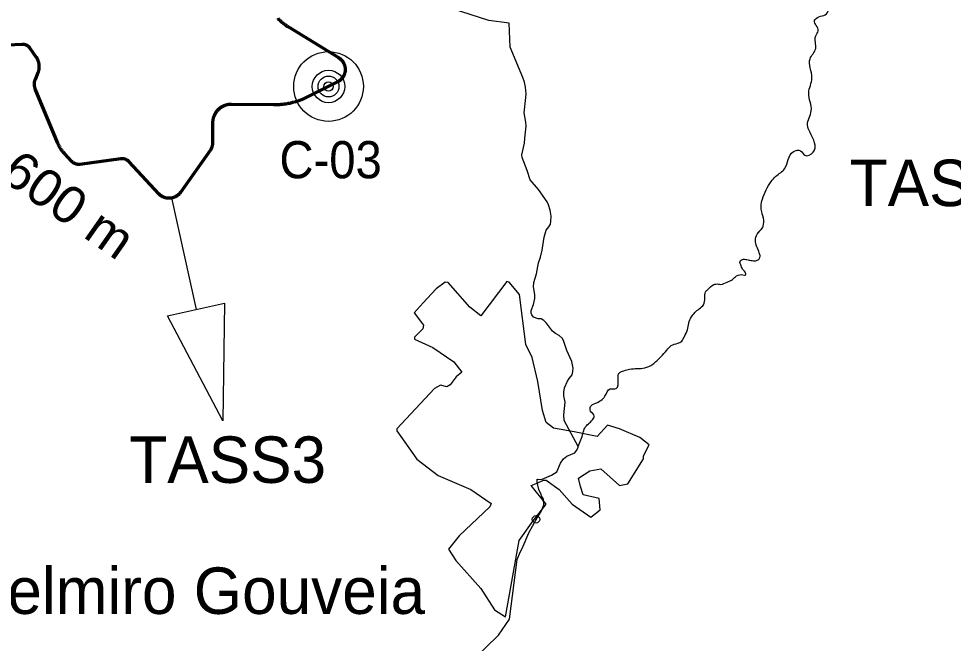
# Model space of a CAD drawing. Extents: x -1643653 to 4543381, y 1624270 to 13878484.
# Drawn here: x 604414 to 614474, y 8960089 to 8966810 of the extents above; entities that cross this region are included whole.
import ezdxf
from ezdxf.enums import TextEntityAlignment as Align

# ---------------------------------------------------------------- set-up
doc = ezdxf.new("R2010")
doc.units = 0
doc.header["$LTSCALE"] = 160
doc.header["$PDMODE"] = 32
doc.header["$PDSIZE"] = 80
for name, color, linetype, lineweight in [('15', 7, 'Continuous', 25), ('21', 7, 'Continuous', 25), ('24', 7, 'Continuous', 25), ('50', 7, 'Continuous', 13), ('54', 7, 'Continuous', 25), ('60', 7, 'Continuous', 13), ('61', 7, 'Continuous', 70)]:
    doc.layers.add(name, color=color, linetype=linetype, lineweight=lineweight)
doc.layers.add('41', color=7, linetype='Continuous')

msp = doc.modelspace()

# ---------------------------------------------------------------- linework, layer by layer
at = {"layer": '15'}
for radius in [375, 175, 112.5, 50]:
    msp.add_circle((607748.5, 8966080.3), radius, dxfattribs=at)
at = {"layer": '21'}
for points in [[(609804.3, 8963841.6), (609692.8, 8963976.2), (609666.6, 8963982.7), (609387.8, 8963613.5), (609268.7, 8963704.3), (609037.7, 8963969.7), (609005.2, 8963976.3), (608907.9, 8963902.9), (608765.2, 8963749.4), (608768.4, 8963752.9)], [(609800.8, 8961196.1), (609951.3, 8961405.5), (610091.2, 8961585.5), (609931.3, 8961785.4), (610001.3, 8961815.4), (610061.2, 8961845.4), (610091.2, 8961845.4), (610231.1, 8961745.4), (610371.1, 8961585.5), (610570.9, 8961445.5), (610670.8, 8961525.5), (610660.9, 8961645.5), (610491, 8961685.5), (610461, 8961775.4), (610441, 8961865.4), (610560.9, 8961945.4), (610680.8, 8961965.4), (610880.7, 8961785.4), (610970.7, 8961805.4), (611140.5, 8962075.3), (611140.5, 8962105.3), (611200.5, 8962225.3), (611100.6, 8962305.2), (610880.7, 8962395.2), (610750.8, 8962435.2), (610640.9, 8962315.2), (610391, 8962365.2), (610171.2, 8962405.2), (610091.2, 8962465.2), (610051.2, 8962595.2), (610001.3, 8962905.1), (609941.3, 8963165), (609871.4, 8963304.9), (609804.3, 8963841.6)], [(608768.4, 8963752.9), (608671.8, 8963644.5), (608771.6, 8963513.5), (608763, 8963472.8), (608674.7, 8963384.3), (608674.6, 8963362.6), (608871.1, 8963271.6), (609098.6, 8963116.9), (609185.2, 8963006.2), (609122.6, 8962955.4), (609059.5, 8962870.7), (609020.3, 8962848.1), (608953.3, 8962867.3), (608890.2, 8962830.9), (608482.3, 8962396.3), (608482.2, 8962374.6), (608698.7, 8962069.7), (608927.4, 8961894.7), (609281.9, 8961745.5), (609500, 8961592.1), (609485, 8961557.5), (609154.4, 8961246.1), (609040.8, 8961101.4), (609119, 8960979.5), (609387.8, 8960677.5), (609534.3, 8960449.1), (609653.8, 8960372.8), (609800.8, 8961196.1)]]:
    msp.add_lwpolyline(points, dxfattribs=at)
at = {"layer": '24'}
for points in [[(609474.2, 8966790.4), (608973.4, 8966950.1), (608864.6, 8966990.5), (608731.8, 8967057), (608620.3, 8967109.1), (608563.4, 8967149.5), (608515.8, 8967162.6)], [(609841.5, 8966176.9), (609704.1, 8966503.7), (609693, 8966762.7), (609474.2, 8966790.4)], [(610371.4, 8962976.2), (610379.8, 8963013.8), (610382.1, 8963047.9), (610367.5, 8963120), (610314.8, 8963239.1), (610282.3, 8963338.2), (610265.4, 8963370.2), (610232.8, 8963402.2), (610193.3, 8963421.2), (610157.8, 8963448.2), (610095.6, 8963532.2), (610066.7, 8963561.2), (610036.6, 8963580.2), (610003.6, 8963581.1), (609956.2, 8963599.1), (609936, 8963623.1), (609928.6, 8963640.1), (609929.5, 8963669.1), (609954.4, 8963735.3), (609968.3, 8963800.4), (609967.7, 8963842.5), (609955.3, 8963923.6), (609957.6, 8963969.7), (609987.3, 8964065.8), (610009.7, 8964184.1), (610029.9, 8964242.2), (610049.4, 8964318.3), (610070.6, 8964459.6), (610090.6, 8964534.7), (610118.8, 8964569.8), (610136.5, 8964599.9), (610143.2, 8964627), (610143.3, 8964686.1), (610132.5, 8964751.1), (610117.5, 8964805.2), (610101.9, 8964839.2), (610009.9, 8964971.3), (609920.5, 8965076.3), (609887.1, 8965177.4), (609832.3, 8965315.6), (609830, 8965343.6), (609859.8, 8965469.8), (609861.1, 8965523.9), (609875.2, 8965654.1), (609872.3, 8965696.2), (609853, 8965796.3), (609874, 8965961.6), (609874.8, 8965999.7), (609869.2, 8966072.8), (609858.8, 8966126.9), (609841.5, 8966176.9)], [(609982.1, 8961422.7), (610037.1, 8961507.9), (610064.5, 8961578.1), (610064.2, 8961638.2), (610040.6, 8961677.2), (610038.1, 8961690.2), (610013.3, 8961743.3), (609992.6, 8961823.3), (609993.5, 8961853.4), (609997.6, 8961856.4), (610025.7, 8961851.5), (610048.1, 8961855.5), (610148.5, 8961896.7), (610207.6, 8961933.9), (610245.1, 8962026.1), (610277.6, 8962073.2), (610312.8, 8962103.3), (610398.6, 8962138.5), (610419.5, 8962164.6), (610435.7, 8962195.6), (610437.2, 8962206.7), (610284.5, 8962485.8), (610279.8, 8962547.9), (610295.5, 8962684.2), (610281.3, 8962752.3), (610279.8, 8962791.3), (610289, 8962838.4), (610320, 8962910.6), (610338.8, 8962938.6), (610371.4, 8962976.2)], [(609306.9, 8959910.2), (609576.6, 8960175.8), (609697.7, 8960350), (609780.5, 8960992), (609809.8, 8961070.9), (609834, 8961110), (609904.8, 8961278.4), (609982.1, 8961422.7)]]:
    msp.add_lwpolyline(points, dxfattribs=at)
msp.add_spline([(610437.2, 8962206.7), (610489.2, 8962352.5), (610507, 8962405.6), (610591.1, 8962494.2), (610608.8, 8962534.1), (610569, 8962587.3), (610569, 8962636), (610622.1, 8962671.5), (610723.9, 8962746.8), (610781.5, 8962826.6), (610843.5, 8962831), (610865.6, 8962932.9), (610878.9, 8962999.4), (610927.6, 8963021.5), (610989.6, 8963039.3), (611153.5, 8963052.6), (611237.6, 8963092.4), (611326.2, 8963170.3), (611391.1, 8963243.8), (611437.2, 8963291.6), (611507.3, 8963317.3), (611551.7, 8963341.2), (611579, 8963390.8), (611611.5, 8963460.9), (611625.2, 8963534.4), (611655.9, 8963601), (611737.9, 8963688.2), (611785.7, 8963732.7), (611797.7, 8963804.5), (611808, 8963871.1), (611830.2, 8963895.1), (611896.8, 8963948.1), (611919, 8963954.9), (611970.2, 8963951.5), (612038.6, 8963975.4), (612098.4, 8964004.5), (612127.4, 8964033.5), (612190.6, 8964055.8), (612224.8, 8964050.6), (612238.5, 8964052.3), (612240.2, 8964069.4), (612206, 8964115.6), (612185.5, 8964161.7), (612177, 8964187.4), (612183.8, 8964207.9), (612226.5, 8964221.6), (612276, 8964211.3), (612310.2, 8964206.2), (612354.6, 8964207.9), (612385.4, 8964225), (612393.9, 8964254), (612385.4, 8964289.9), (612343.5, 8964423.3), (612364, 8964491.7), (612418.7, 8964560.1), (612432.3, 8964642.1), (612411.8, 8964731), (612405, 8964792.5), (612418.7, 8964867.8), (612514.3, 8965059.2), (612562.2, 8965113.9), (612657.8, 8965196), (612753.5, 8965380.6), (612828.7, 8965387.4), (612876.5, 8965339.6), (612965.4, 8965373.7), (612931.2, 8965585.7), (612903.9, 8965667.8), (612944.9, 8965818.2), (612917.5, 8966009.7), (612951.7, 8966173.8), (612931.2, 8966378.9), (612992.7, 8966488.3), (612992.7, 8966625.1), (613020, 8966679.8), (612979, 8966789.2), (613026.9, 8966830.2), (613095.2, 8966850.7), (613136.2, 8967014.8), (613067.9, 8967213.1), (612965.4, 8967261), (612938, 8967343), (612883.4, 8967397.7), (612787.7, 8967425.1), (612753.5, 8967452.4), (612705.7, 8967520.8), (612658.6, 8967543.9), (612640.1, 8967590.1), (612640.1, 8967642.6), (612667.9, 8967707.3), (612667.9, 8967747.4)], degree=3, dxfattribs=at)
msp.add_point((609982.1, 8961422.7), dxfattribs=at)
at = {"layer": '54'}
msp.add_line((606056.9, 8964881.6), (606322.4, 8963679.5), dxfattribs=at)
msp.add_lwpolyline([(606630.7, 8963747.6), (606609.7, 8962482.2), (606014.1, 8963611.4)], close=True, dxfattribs=at)
at = {"layer": '60', "lineweight": 25}
msp.add_spline([(814781, 9009175.5), (814787.2, 9009173.4), (814796.9, 9009173.4), (814799.4, 9009172.4), (814805.1, 9009174.5), (814805.6, 9009176.5), (814811.7, 9009179.5), (814811.7, 9009179.5), (814801.5, 9009181), (814790.7, 9009181.5), (814784.1, 9009183.1), (814777.4, 9009185.1), (814778.4, 9009175.5)], degree=3, dxfattribs=at)
at = {"layer": '61'}
for points in [[(607201.7, 8966814), (607206.5, 8966809.1), (607211.4, 8966804.2), (607216.4, 8966799.4), (607221.4, 8966794.6), (607226.5, 8966789.9), (607231.6, 8966785.3), (607236.8, 8966780.7), (607242.1, 8966776.1), (607247.3, 8966771.7), (607252.7, 8966767.2), (607258.1, 8966762.9), (607263.5, 8966758.6), (607269, 8966754.4), (607274.6, 8966750.2), (607280.2, 8966746.1), (607285.8, 8966742.1), (607291.5, 8966738.2), (607297.2, 8966734.2), (607303, 8966730.4), (607308.8, 8966726.7), (607314.7, 8966723), (607318.3, 8966720.7), (607318.3, 8966720.7), (607856.3, 8966390.9), (607856.3, 8966390.9), (607859.2, 8966389), (607862.1, 8966387.1), (607864.9, 8966385.1), (607867.7, 8966383.1), (607870.5, 8966381), (607873.2, 8966378.8), (607875.8, 8966376.6), (607878.4, 8966374.3), (607881, 8966371.9), (607883.5, 8966369.5), (607885.9, 8966367.1), (607888.3, 8966364.5), (607890.6, 8966362), (607892.8, 8966359.3), (607895, 8966356.6), (607897.2, 8966353.9), (607899.2, 8966351.1), (607901.2, 8966348.3), (607903.2, 8966345.4), (607905, 8966342.5), (607906.8, 8966339.6), (607908.6, 8966336.6), (607910.2, 8966333.5), (607911.8, 8966330.5), (607913.3, 8966327.3), (607914.8, 8966324.2), (607916.2, 8966321), (607917.5, 8966317.8), (607918.7, 8966314.6), (607919.9, 8966311.3), (607920.9, 8966308), (607921.9, 8966304.7), (607922.9, 8966301.3), (607923.7, 8966298), (607924.5, 8966294.6), (607925.2, 8966291.2), (607925.8, 8966287.8), (607926.3, 8966284.4), (607926.8, 8966281), (607927.2, 8966277.5), (607927.5, 8966274.1), (607927.7, 8966270.6), (607927.8, 8966267.1), (607927.9, 8966263.7), (607927.8, 8966260.2), (607927.7, 8966256.8), (607927.6, 8966253.3), (607927.3, 8966249.8), (607926.9, 8966246.4), (607926.5, 8966243), (607926, 8966239.5), (607925.4, 8966236.1), (607924.8, 8966232.7), (607924, 8966229.3), (607923.2, 8966226), (607922.3, 8966222.6), (607921.3, 8966219.3), (607920.3, 8966216), (607919.2, 8966212.7), (607918, 8966209.5), (607916.7, 8966206.2), (607915.4, 8966203), (607913.9, 8966199.9), (607912.5, 8966196.8), (607910.9, 8966193.7), (607909.2, 8966190.6), (607907.5, 8966187.6), (607905.8, 8966184.6), (607903.9, 8966181.7), (607902, 8966178.8), (607900, 8966176), (607898, 8966173.2)], [(604629, 8966245.2), (604630, 8966248.8), (604630.8, 8966252.5), (604631.7, 8966256.2), (604632.4, 8966260), (604633.1, 8966263.7), (604633.7, 8966267.4), (604634.2, 8966271.2), (604634.7, 8966275), (604635, 8966278.7), (604635.3, 8966282.5), (604635.5, 8966286.3), (604635.6, 8966290.1), (604635.6, 8966293.9), (604635.6, 8966297.7), (604635.5, 8966301.5), (604635.3, 8966305.3), (604635, 8966309.1), (604634.6, 8966312.8), (604634.2, 8966316.6), (604633.6, 8966320.4), (604633, 8966324.1), (604632.4, 8966327.8), (604631.6, 8966331.6), (604630.8, 8966335.3), (604629.8, 8966339), (604628.9, 8966342.6), (604627.8, 8966346.2), (604626.6, 8966349.9), (604625.4, 8966353.5), (604624.1, 8966357), (604622.8, 8966360.6), (604621.3, 8966364.1), (604619.8, 8966367.6), (604618.2, 8966371), (604616.5, 8966374.4), (604614.8, 8966377.8), (604613, 8966381.1), (604611.1, 8966384.4), (604609.2, 8966387.7), (604607.1, 8966390.9), (604605.1, 8966394.1), (604603.5, 8966396.4), (604603.5, 8966396.4), (604538.6, 8966489.8), (604536.9, 8966492.1), (604535.2, 8966494.3), (604533.5, 8966496.6), (604531.6, 8966498.7), (604529.7, 8966500.8), (604527.8, 8966502.8), (604525.8, 8966504.8), (604523.7, 8966506.8), (604521.6, 8966508.7), (604519.4, 8966510.5), (604517.2, 8966512.2), (604514.9, 8966513.9), (604512.6, 8966515.5), (604510.2, 8966517.1), (604507.8, 8966518.6), (604505.4, 8966520), (604502.9, 8966521.3), (604500.4, 8966522.6), (604497.8, 8966523.8), (604495.2, 8966524.9), (604492.6, 8966526), (604489.9, 8966527), (604487.3, 8966527.9), (604484.6, 8966528.7), (604481.8, 8966529.5), (604479.1, 8966530.2), (604476.3, 8966530.8), (604473.6, 8966531.3), (604470.8, 8966531.7), (604468, 8966532.1), (604465.1, 8966532.4), (604462.3, 8966532.6), (604459.5, 8966532.7), (604456.7, 8966532.8), (604453.8, 8966532.7), (604451.6, 8966532.6), (604451.6, 8966532.6), (604208.1, 8966520.9)], [(605060.5, 8965241.8), (605057.7, 8965241.8), (605054.9, 8965241.9), (605052.1, 8965242), (605049.2, 8965242.3), (605046.4, 8965242.6), (605043.6, 8965243), (605040.8, 8965243.4), (605038.1, 8965244), (605035.3, 8965244.6), (605032.6, 8965245.3), (605029.8, 8965246.1), (605027.1, 8965246.9), (605024.5, 8965247.8), (605021.8, 8965248.8), (605019.2, 8965249.9), (605016.6, 8965251.1), (605014.1, 8965252.3), (605011.6, 8965253.6), (605009.1, 8965254.9), (605006.6, 8965256.4), (605004.2, 8965257.9), (605001.9, 8965259.4), (604999.6, 8965261.1), (604997.3, 8965262.8), (604995.1, 8965264.5), (604992.9, 8965266.4), (604990.8, 8965268.2), (604988.8, 8965270.2), (604986.8, 8965272.2), (604985.2, 8965273.9), (604907.2, 8965358.2), (604903.3, 8965362.3), (604899.6, 8965366.6), (604895.9, 8965370.8), (604892.3, 8965375.2), (604888.7, 8965379.6), (604885.2, 8965384), (604881.7, 8965388.5), (604878.4, 8965393), (604875, 8965397.6), (604871.8, 8965402.2), (604868.6, 8965406.9), (604865.5, 8965411.6), (604862.4, 8965416.4), (604859.4, 8965421.2), (604856.5, 8965426), (604853.7, 8965430.9), (604850.9, 8965435.8), (604848.2, 8965440.8), (604845.6, 8965445.8), (604843, 8965450.9), (604840.5, 8965455.9), (604838.1, 8965461.1), (604835.7, 8965466.2), (604833.4, 8965471.4), (604831.2, 8965476.6), (604830.8, 8965477.7), (604592.6, 8966056.5), (604592.6, 8966056.5), (604591.4, 8966059.5), (604590.3, 8966062.5), (604589.3, 8966065.6), (604588.3, 8966068.6), (604587.4, 8966071.7), (604586.6, 8966074.8), (604585.9, 8966078), (604585.2, 8966081.1), (604584.7, 8966084.3), (604584.2, 8966087.5), (604583.7, 8966090.7), (604583.4, 8966093.9), (604583.2, 8966097.1), (604583, 8966100.3), (604582.9, 8966103.6), (604582.8, 8966106.8), (604582.9, 8966110), (604583.1, 8966113.2), (604583.3, 8966116.5), (604583.6, 8966119.7), (604584, 8966122.9), (604584.4, 8966126.1), (604585, 8966129.2), (604585.6, 8966132.4), (604586.3, 8966135.6), (604587, 8966138.7), (604587.9, 8966141.8), (604588.8, 8966144.9), (604589.8, 8966148), (604590.9, 8966151), (604592.1, 8966154), (604593.1, 8966156.5), (604593.1, 8966156.5), (604621.5, 8966223.7), (604621.5, 8966223.7), (604622.9, 8966227.2), (604624.3, 8966230.8), (604625.6, 8966234.3), (604626.8, 8966237.9), (604627.9, 8966241.5), (604629, 8966245.2)], [(607898, 8966173.2), (607895.9, 8966170.4), (607893.7, 8966167.7), (607891.5, 8966165.1), (607889.2, 8966162.5), (607886.8, 8966159.9), (607884.4, 8966157.4), (607882, 8966155), (607879.5, 8966152.6), (607876.9, 8966150.3), (607874.2, 8966148.1), (607871.6, 8966145.8), (607868.8, 8966143.7), (607866.1, 8966141.7), (607863.2, 8966139.7), (607860.4, 8966137.7), (607857.5, 8966135.8), (607854.5, 8966134), (607851.5, 8966132.3), (607848.5, 8966130.6), (607845.4, 8966129), (607845.2, 8966129), (607524, 8965967.5), (607516.8, 8965963.9), (607509.6, 8965960.4), (607502.4, 8965957), (607495.1, 8965953.7), (607487.8, 8965950.4), (607480.5, 8965947.2), (607473.1, 8965944.1), (607465.7, 8965941), (607458.3, 8965938.1), (607450.8, 8965935.2), (607443.4, 8965932.3), (607435.8, 8965929.6), (607428.3, 8965926.9), (607420.7, 8965924.3), (607413.2, 8965921.8), (607405.5, 8965919.4), (607397.9, 8965917), (607390.2, 8965914.7), (607382.5, 8965912.5), (607374.8, 8965910.3), (607367.1, 8965908.3), (607359.4, 8965906.3), (607351.6, 8965904.4), (607343.8, 8965902.6), (607336, 8965900.8), (607328.2, 8965899.1), (607320.3, 8965897.5), (607312.5, 8965896), (607304.6, 8965894.6), (607296.7, 8965893.2), (607288.8, 8965891.9), (607280.9, 8965890.7), (607273, 8965889.6), (607265.1, 8965888.6), (607257.1, 8965887.6), (607249.2, 8965886.7), (607241.2, 8965885.9), (607233.2, 8965885.2), (607225.3, 8965884.5), (607217.3, 8965884), (607209.3, 8965883.5), (607201.3, 8965883.1), (607193.3, 8965882.8), (607185.3, 8965882.5), (607177.3, 8965882.3), (607169.3, 8965882.2), (607161.3, 8965882.2), (607155.3, 8965882.3), (606702.8, 8965887.6), (606698.8, 8965887.6), (606694.8, 8965887.6), (606690.8, 8965887.4), (606686.8, 8965887.2), (606682.8, 8965886.8), (606678.8, 8965886.5), (606674.8, 8965886), (606670.9, 8965885.4), (606666.9, 8965884.8), (606663, 8965884.1), (606659.1, 8965883.3), (606655.2, 8965882.4), (606651.3, 8965881.5), (606647.4, 8965880.5), (606643.6, 8965879.4), (606639.8, 8965878.2), (606636, 8965877), (606632.2, 8965875.6), (606628.4, 8965874.2), (606624.7, 8965872.7), (606621, 8965871.2), (606617.4, 8965869.6), (606613.8, 8965867.9), (606610.2, 8965866.1), (606606.6, 8965864.3), (606603.1, 8965862.3), (606599.6, 8965860.4), (606596.2, 8965858.3), (606592.8, 8965856.2)], [(606592.8, 8965856.2), (606589.5, 8965854), (606586.2, 8965851.8), (606582.9, 8965849.4), (606579.7, 8965847.1), (606576.5, 8965844.6), (606573.4, 8965842.1), (606570.3, 8965839.5), (606567.3, 8965836.9), (606564.4, 8965834.2), (606561.5, 8965831.5), (606558.6, 8965828.7), (606555.8, 8965825.8), (606553.1, 8965822.9), (606550.4, 8965819.9), (606547.8, 8965816.9), (606545.2, 8965813.8), (606542.8, 8965810.7), (606540.3, 8965807.5), (606538, 8965804.2), (606535.7, 8965801), (606533.4, 8965797.7), (606531.2, 8965794.3), (606529.2, 8965790.9), (606527.1, 8965787.5), (606525.2, 8965784), (606523.3, 8965780.4), (606521.5, 8965776.9), (606519.7, 8965773.3), (606518, 8965769.7), (606516.4, 8965766), (606514.9, 8965762.3), (606513.4, 8965758.6), (606512.1, 8965754.8), (606510.8, 8965751), (606509.5, 8965747.2), (606508.4, 8965743.4), (606507.3, 8965739.5), (606506.3, 8965735.7), (606505.4, 8965731.8), (606504.5, 8965727.9), (606503.8, 8965723.9), (606503.1, 8965720), (606502.5, 8965716), (606501.9, 8965712.1), (606501.5, 8965708.1), (606501.1, 8965704.1), (606500.8, 8965700.1), (606500.6, 8965696.1), (606500.5, 8965692.1), (606500.4, 8965688.1), (606500.4, 8965687.2), (606500.9, 8965478.6), (606500.9, 8965478.6), (606500.8, 8965475.2), (606500.7, 8965471.7), (606500.5, 8965468.2), (606500.3, 8965464.8), (606499.9, 8965461.3), (606499.5, 8965457.9), (606499, 8965454.5), (606498.4, 8965451.1), (606497.7, 8965447.7), (606497, 8965444.3), (606496.1, 8965440.9), (606495.2, 8965437.6), (606494.3, 8965434.2), (606493.2, 8965430.9), (606492.1, 8965427.7), (606490.9, 8965424.4), (606489.6, 8965421.2), (606488.2, 8965418), (606486.8, 8965414.9), (606485.3, 8965411.7), (606483.7, 8965408.7), (606482.1, 8965405.6), (606480.4, 8965402.6), (606478.6, 8965399.6), (606476.7, 8965396.7), (606474.8, 8965393.8), (606473.4, 8965391.8), (606473.4, 8965391.8), (606154.7, 8964940.6), (606152.7, 8964937.8), (606150.6, 8964935), (606148.4, 8964932.3), (606146.2, 8964929.6), (606143.9, 8964927), (606141.6, 8964924.5), (606139.2, 8964922), (606136.7, 8964919.5), (606134.2, 8964917.2), (606131.6, 8964914.8), (606129, 8964912.6), (606126.3, 8964910.3), (606123.6, 8964908.2), (606120.9, 8964906.1), (606118, 8964904.1), (606115.2, 8964902.2), (606112.3, 8964900.3), (606109.3, 8964898.5)], [(606109.3, 8964898.5), (606106.3, 8964896.7), (606103.3, 8964895), (606100.2, 8964893.4), (606097.1, 8964891.9), (606094, 8964890.4), (606090.8, 8964889), (606087.6, 8964887.7), (606084.4, 8964886.5), (606081.1, 8964885.3), (606077.8, 8964884.2), (606074.5, 8964883.2), (606071.2, 8964882.3), (606067.8, 8964881.4), (606064.5, 8964880.6), (606061.1, 8964879.9), (606057.7, 8964879.3), (606054.2, 8964878.7), (606050.8, 8964878.3), (606047.4, 8964877.9), (606043.9, 8964877.6), (606040.5, 8964877.3), (606037, 8964877.2), (606033.5, 8964877.1), (606030.1, 8964877.1), (606026.6, 8964877.2), (606023.1, 8964877.4), (606019.7, 8964877.6), (606016.2, 8964878), (606012.8, 8964878.4), (606009.4, 8964878.8), (606006, 8964879.4), (606002.5, 8964880.1), (605999.2, 8964880.8), (605995.8, 8964881.6), (605992.4, 8964882.5), (605989.1, 8964883.4), (605985.8, 8964884.5), (605982.5, 8964885.6), (605979.3, 8964886.8), (605976, 8964888), (605972.8, 8964889.3), (605969.7, 8964890.8), (605966.5, 8964892.2), (605963.4, 8964893.8), (605960.4, 8964895.4), (605957.4, 8964897.1), (605954.4, 8964898.9), (605951.4, 8964900.7), (605948.5, 8964902.6), (605945.7, 8964904.6), (605942.9, 8964906.6), (605940.1, 8964908.7), (605937.4, 8964910.8), (605934.8, 8964913.1), (605932.1, 8964915.3), (605929.6, 8964917.7), (605927.1, 8964920.1), (605924.7, 8964922.5), (605922.3, 8964925), (605922.2, 8964925.1), (605601.3, 8965270.9), (605599.4, 8965272.9), (605597.4, 8965274.9), (605595.3, 8965276.8), (605593.2, 8965278.7), (605591, 8965280.5), (605588.8, 8965282.3), (605586.5, 8965284), (605584.2, 8965285.6), (605581.8, 8965287.1), (605579.5, 8965288.6), (605577, 8965290), (605574.5, 8965291.4), (605572, 8965292.7), (605569.4, 8965293.9), (605566.8, 8965295), (605564.2, 8965296.1), (605561.6, 8965297.1), (605558.9, 8965298), (605556.2, 8965298.8), (605553.5, 8965299.6), (605550.7, 8965300.2), (605548, 8965300.8), (605545.2, 8965301.4), (605542.4, 8965301.8), (605539.6, 8965302.2), (605536.8, 8965302.5), (605533.9, 8965302.7), (605531.1, 8965302.8), (605528.3, 8965302.8), (605525.5, 8965302.8), (605522.6, 8965302.7), (605519.8, 8965302.5), (605517, 8965302.2), (605514.8, 8965302), (605071.8, 8965242.7), (605069, 8965242.4), (605066.2, 8965242.1), (605063.4, 8965242), (605060.5, 8965241.8)]]:
    msp.add_lwpolyline(points, dxfattribs=at)

# ---------------------------------------------------------------- texts
at = {"layer": '15', "width": 0.95}
msp.add_text('C-03', height=400, dxfattribs=at).set_placement((607220.4, 8965092.8))
at = {"layer": '41'}
msp.add_text('Delmiro Gouveia', height=500, dxfattribs=at).set_placement((603808.9, 8960405.2))
at = {"layer": '50', "width": 1.05}
msp.add_text('L=8.600 m', height=400, rotation=325.018, dxfattribs=at).set_placement((603290.8, 8965729.8))
at = {"layer": '54'}
for s, p in [('TASS4', (614417.6, 8964793.2)), ('TASS3', (606663.7, 8961815.1))]:
    msp.add_text(s, height=500, dxfattribs=at).set_placement(p, align=Align.CENTER)

doc.saveas('drawing.dxf')
